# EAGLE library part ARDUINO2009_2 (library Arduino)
The Arduino Duemilanove ("2009") is a microcontroller board based on the ATmega168 or ATmega328. - 14 digital input/output pins (of which 6 can be used as PWM outputs) - 6 analog inputs, a 16 MHz crystal oscillator - USB connection - power jack - ISP header - reset button It contains everything needed to support the microcontroller; simply connect it to a computer with a USB cable or power it with a AC-to-DC adapter or battery to get started http://arduino.cc/en/Main/ArduinoBoardDuemilanove
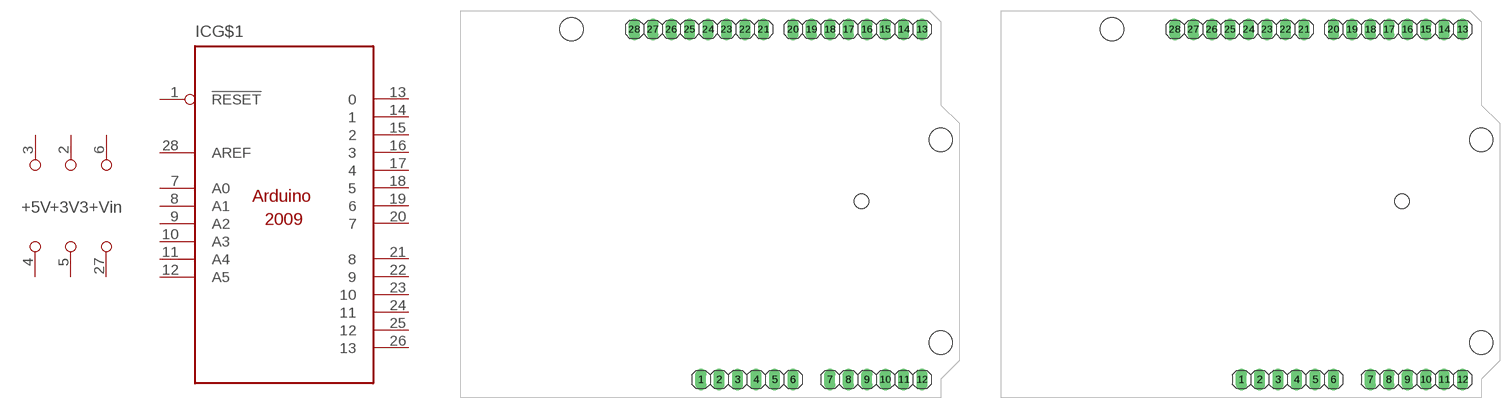
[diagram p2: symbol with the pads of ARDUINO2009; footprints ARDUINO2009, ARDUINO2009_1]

Designator prefix IC; gates G$1=ARDUNIO2009_1 G$2=PWR5V G$3=PWR3V3 G$4=PWRVIN

## ARDUINO2009_20  [ARDUINO2009]
1  G$1:!RESET
2  G$3:+3V3  pwr
3  G$2:+5V  pwr
4  G$2:GND  pwr
5  G$3:GND  pwr
6  G$4:+VIN  pwr
7  G$1:A0
8  G$1:A1
9  G$1:A2
10  G$1:A3
11  G$1:A4
12  G$1:A5
13  G$1:0
14  G$1:1
15  G$1:2
16  G$1:3
17  G$1:4
18  G$1:5
19  G$1:6
20  G$1:7
21  G$1:8
22  G$1:9
23  G$1:10
24  G$1:11
25  G$1:12
26  G$1:13
27  G$4:GND  pwr
28  G$1:AREF

## ARDUINO2009_21  [ARDUINO2009_1]
Pads as for ARDUINO2009

## ARDUINO2009_22  [ARDUINO2009_2]
Pads as for ARDUINO2009

## Footprint ARDUINO2009 (pad centres in mm)
drill 1.016 long: 1 33.02,2.54; 2 35.56,2.54; 3 38.1,2.54; 4 40.64,2.54; 5 43.18,2.54; 6 45.72,2.54; 7 50.8,2.54; 8 53.34,2.54; 9 55.88,2.54; 10 58.42,2.54; 11 60.96,2.54; 12 63.5,2.54; 13 63.5,50.8; 14 60.96,50.8; 15 58.42,50.8; 16 55.88,50.8; 17 53.34,50.8; 18 50.8,50.8; 19 48.26,50.8; 20 45.72,50.8; 21 41.656,50.8; 22 39.116,50.8; 23 36.576,50.8; 24 34.036,50.8; 25 31.496,50.8; 26 28.956,50.8; 27 26.416,50.8; 28 23.876,50.8
hole 3.2 at 15.24,50.8
hole 3.2 at 66.04,35.56
hole 3.2 at 66.04,7.62
hole 2 at 55.17,27.114

## Footprint ARDUINO2009_1 (pad centres in mm)
drill 1.016 long: 1 33.02,2.54; 2 35.56,2.54; 3 38.1,2.54; 4 40.64,2.54; 5 43.18,2.54; 6 45.72,2.54; 7 50.8,2.54; 8 53.34,2.54; 9 55.88,2.54; 10 58.42,2.54; 11 60.96,2.54; 12 63.5,2.54; 13 63.5,50.8; 14 60.96,50.8; 15 58.42,50.8; 16 55.88,50.8; 17 53.34,50.8; 18 50.8,50.8; 19 48.26,50.8; 20 45.72,50.8; 21 41.656,50.8; 22 39.116,50.8; 23 36.576,50.8; 24 34.036,50.8; 25 31.496,50.8; 26 28.956,50.8; 27 26.416,50.8; 28 23.876,50.8
hole 3.2 at 15.24,50.8
hole 3.2 at 66.04,35.56
hole 3.2 at 66.04,7.62
hole 2 at 55.17,27.114

## Footprint ARDUINO2009_2 (pad centres in mm)
drill 1.016 long: 1 33.02,2.54; 2 35.56,2.54; 3 38.1,2.54; 4 40.64,2.54; 5 43.18,2.54; 6 45.72,2.54; 7 50.8,2.54; 8 53.34,2.54; 9 55.88,2.54; 10 58.42,2.54; 11 60.96,2.54; 12 63.5,2.54; 13 63.5,50.8; 14 60.96,50.8; 15 58.42,50.8; 16 55.88,50.8; 17 53.34,50.8; 18 50.8,50.8; 19 48.26,50.8; 20 45.72,50.8; 21 41.656,50.8; 22 39.116,50.8; 23 36.576,50.8; 24 34.036,50.8; 25 31.496,50.8; 26 28.956,50.8; 27 26.416,50.8; 28 23.876,50.8
hole 3.2 at 15.24,50.8
hole 3.2 at 66.04,35.56
hole 3.2 at 66.04,7.62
